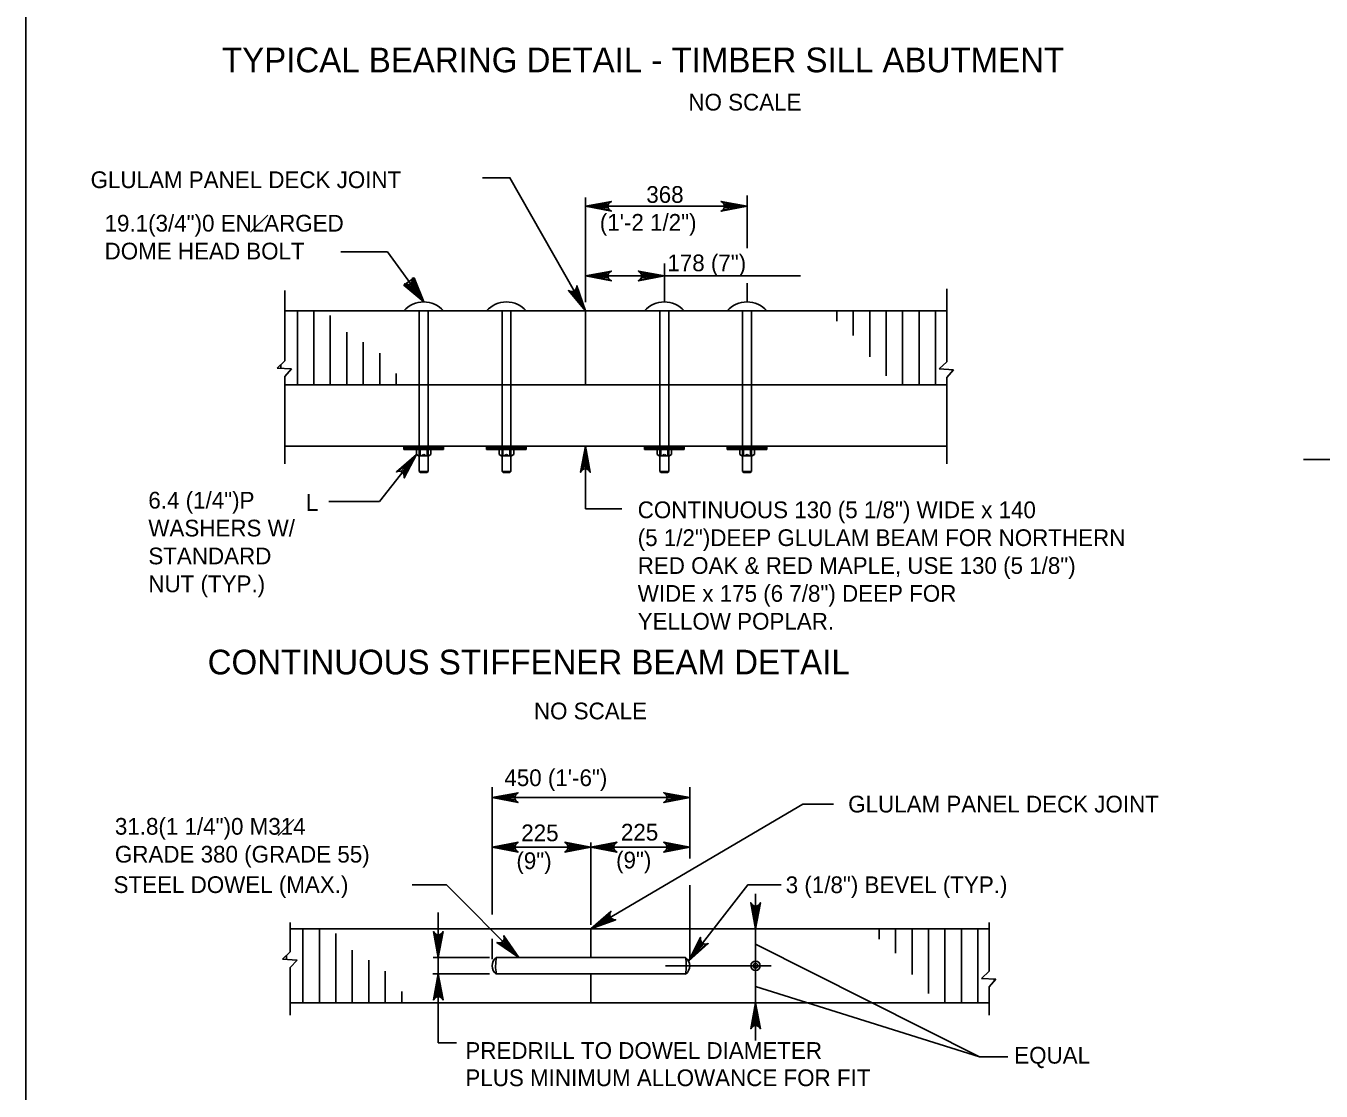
# Model space of a CAD drawing. Extents: x 638268 to 640277, y 295465 to 298435.
# Drawn here: x 639316.5 to 639548.8, y 296279.1 to 296470.2 of the extents above; entities that cross this region are included whole.
import ezdxf

# ---------------------------------------------------------------- set-up
doc = ezdxf.new("R2010")
doc.units = 0
for name, color, linetype in [('2', 7, 'Continuous'), ('3', 7, 'Continuous'), ('5', 7, 'Continuous')]:
    doc.layers.add(name, color=color, linetype=linetype)

msp = doc.modelspace()

# ---------------------------------------------------------------- linework, layer by layer
at = {"layer": '2'}
for p, q in [((639316.46, 296074.46), (639316.46, 296638.46)), ((639381.31, 296429.69), (639372.97, 296429.69)), ((639387.81, 296420.68), (639381.31, 296429.69)), ((639481.65, 296423.01), (639481.65, 296409.95)), ((639362.88, 296422.75), (639362.88, 296410.1)), ((639362.88, 296419.08), (639481.65, 296419.08)), ((639387.81, 296419.08), (639384.24, 296419.08)), ((639387.02, 296390.27), (639387.02, 296419.08)), ((639387.81, 296419.08), (639391.38, 296419.08)), ((639388.6, 296419.08), (639388.6, 296390.27)), ((639401.86, 296390.27), (639401.86, 296419.08)), ((639403.43, 296419.08), (639403.43, 296390.27)), ((639416.81, 296405.8), (639416.81, 296419.08)), ((639430.19, 296390.27), (639430.19, 296419.08)), ((639431.76, 296419.08), (639431.76, 296390.27)), ((639445.02, 296390.27), (639445.02, 296419.08)), ((639446.6, 296419.08), (639446.6, 296390.27)), ((639362.88, 296410.1), (639361.5, 296408.8)), ((639481.65, 296409.95), (639480.27, 296408.65)), ((639361.5, 296408.8), (639364.1, 296408.66)), ((639364.1, 296408.66), (639362.88, 296407.29)), ((639362.88, 296407.29), (639362.88, 296391.6)), ((639480.27, 296408.65), (639482.87, 296408.51)), ((639482.87, 296408.51), (639481.65, 296407.14)), ((639481.65, 296407.14), (639481.65, 296391.6)), ((639362.88, 296405.8), (639481.65, 296405.8)), ((639362.88, 296394.77), (639481.65, 296394.77)), ((639386.51, 296394.18), (639386.51, 296393.29)), ((639389.12, 296394.18), (639386.51, 296394.18)), ((639386.51, 296393.29), (639386.88, 296393.07)), ((639386.88, 296393.07), (639388.74, 296393.07)), ((639387.2, 296393.07), (639387.2, 296394.18)), ((639388.43, 296393.07), (639388.43, 296394.18)), ((639388.74, 296393.07), (639389.12, 296393.29)), ((639389.12, 296394.18), (639389.12, 296393.29)), ((639403.95, 296394.18), (639401.34, 296394.18)), ((639401.34, 296394.18), (639401.34, 296393.29)), ((639401.34, 296393.29), (639401.72, 296393.07)), ((639401.72, 296393.07), (639403.57, 296393.07)), ((639402.03, 296393.07), (639402.03, 296394.18)), ((639403.26, 296393.07), (639403.26, 296394.18)), ((639403.57, 296393.07), (639403.95, 296393.29)), ((639403.95, 296394.18), (639403.95, 296393.29)), ((639432.28, 296394.18), (639429.67, 296394.18)), ((639429.67, 296394.18), (639429.67, 296393.29)), ((639429.67, 296393.29), (639430.05, 296393.07)), ((639430.05, 296393.07), (639431.9, 296393.07)), ((639430.36, 296393.07), (639430.36, 296394.18)), ((639431.59, 296393.07), (639431.59, 296394.18)), ((639431.9, 296393.07), (639432.28, 296393.29)), ((639432.28, 296394.18), (639432.28, 296393.29)), ((639447.12, 296394.18), (639444.51, 296394.18)), ((639444.51, 296394.18), (639444.51, 296393.29)), ((639444.51, 296393.29), (639444.88, 296393.07)), ((639444.88, 296393.07), (639446.74, 296393.07)), ((639445.2, 296393.07), (639445.2, 296394.18)), ((639446.43, 296393.07), (639446.43, 296394.18)), ((639446.74, 296393.07), (639447.12, 296393.29)), ((639447.12, 296394.18), (639447.12, 296393.29)), ((639387.22, 296390.07), (639387.02, 296390.27)), ((639388.6, 296390.27), (639387.02, 296390.27)), ((639388.4, 296390.07), (639387.22, 296390.07)), ((639388.6, 296390.27), (639388.4, 296390.07)), ((639403.43, 296390.27), (639401.86, 296390.27)), ((639402.05, 296390.07), (639401.86, 296390.27)), ((639403.24, 296390.07), (639402.05, 296390.07)), ((639403.43, 296390.27), (639403.24, 296390.07)), ((639431.76, 296390.27), (639430.19, 296390.27)), ((639430.38, 296390.07), (639430.19, 296390.27)), ((639431.57, 296390.07), (639430.38, 296390.07)), ((639431.76, 296390.27), (639431.57, 296390.07)), ((639446.6, 296390.27), (639445.02, 296390.27)), ((639445.22, 296390.07), (639445.02, 296390.27)), ((639446.4, 296390.07), (639445.22, 296390.07)), ((639446.6, 296390.27), (639446.4, 296390.07)), ((639363.88, 296309.32), (639363.88, 296304.05)), ((639489.23, 296309.32), (639489.23, 296300.61)), ((639363.88, 296308.22), (639489.23, 296308.22)), ((639417.81, 296303.05), (639417.81, 296308.22)), ((639363.88, 296304.05), (639362.5, 296302.75)), ((639362.5, 296302.75), (639365.1, 296302.6)), ((639365.1, 296302.6), (639363.88, 296301.24)), ((639363.88, 296301.24), (639363.88, 296292.73)), ((639417.81, 296294.93), (639417.81, 296300.1)), ((639489.23, 296300.61), (639487.86, 296299.3)), ((639487.86, 296299.3), (639490.46, 296299.16)), ((639490.46, 296299.16), (639489.23, 296297.79)), ((639489.23, 296297.79), (639489.23, 296292.73)), ((639363.88, 296294.93), (639489.23, 296294.93))]:
    msp.add_line(p, q, dxfattribs=at)
for points in [[(639387.81, 296420.68), (639386.09, 296424.99), (639384.27, 296423.67)], [(639435.31, 296302.43), (639435.4, 296302.51), (639435.36, 296302.54)]]:
    msp.add_lwpolyline(points, close=True, dxfattribs=at)
msp.add_lwpolyline([(639435.31, 296302.43), (639445.93, 296316.07), (639451.95, 296316.07)], dxfattribs=at)
for centre, radius, start, end in [((639387.81, 296415.89), 4.79, 41.8701, 138.1299), ((639387.16, 296394.16), 1.08, 233, 307), ((639388.46, 296394.16), 1.08, 233, 307), ((639401.99, 296394.16), 1.08, 233, 307), ((639403.3, 296394.16), 1.08, 233, 307), ((639430.32, 296394.16), 1.08, 233, 307), ((639431.63, 296394.16), 1.08, 233, 307), ((639445.16, 296394.16), 1.08, 233, 307), ((639446.46, 296394.16), 1.08, 233, 307)]:
    msp.add_arc(centre, radius, start, end, dxfattribs=at)
at = {"layer": '3'}
for p, q in [((639356.76, 296433.17), (639359.83, 296436.24)), ((639379.86, 296384.86), (639370.8, 296384.86)), ((639416.81, 296383.57), (639423.36, 296383.57)), ((639400.09, 296310.78), (639400.09, 296333.61)), ((639435.53, 296320.85), (639435.53, 296333.61)), ((639400.09, 296331.74), (639435.53, 296331.74)), ((639361.71, 296324.97), (639364.53, 296327.79)), ((639417.81, 296308.94), (639417.81, 296323.67)), ((639400.09, 296322.86), (639435.53, 296322.86)), ((639385.76, 296316.09), (639391.89, 296316.09)), ((639404.87, 296303.05), (639391.89, 296316.09)), ((639435.53, 296302.73), (639435.53, 296316.06)), ((639447.34, 296314.49), (639447.34, 296288.17)), ((639390.41, 296311.14), (639390.41, 296287.74)), ((639400.09, 296302.73), (639400.09, 296306.42)), ((639447.34, 296305.48), (639487.49, 296285.22)), ((639399.6, 296303.05), (639389.49, 296303.05)), ((639399.6, 296300.1), (639389.44, 296300.1)), ((639450.14, 296301.58), (639431.2, 296301.58)), ((639447.34, 296297.84), (639487.49, 296285.22)), ((639390.41, 296287.74), (639393.7, 296287.74)), ((639487.49, 296285.22), (639492.62, 296285.22))]:
    msp.add_line(p, q, dxfattribs=at)
for points in [[(639416.81, 296419.08), (639403.28, 296442.95), (639398.36, 296442.95)], [(639387.81, 296420.68), (639384.38, 296423.95), (639384.79, 296423.8), (639385.15, 296423.83), (639385.43, 296423.97), (639385.66, 296424.2), (639385.8, 296424.53), (639385.79, 296424.97), (639387.81, 296420.68), (639385.8, 296424.53), (639385.66, 296424.2), (639387.81, 296420.68), (639385.43, 296423.97), (639385.15, 296423.83), (639387.81, 296420.68), (639384.79, 296423.8)], [(639416.81, 296419.08), (639413.76, 296422.72), (639414.16, 296422.53), (639414.52, 296422.52), (639414.82, 296422.63), (639415.06, 296422.82), (639415.25, 296423.14), (639415.29, 296423.57), (639416.81, 296419.08), (639415.25, 296423.14), (639415.06, 296422.82), (639416.81, 296419.08), (639414.82, 296422.63), (639414.52, 296422.52), (639416.81, 296419.08), (639414.16, 296422.53)], [(639386.51, 296393.29), (639379.86, 296384.86)], [(639386.51, 296393.29), (639384.31, 296389.09), (639384.33, 296389.53), (639384.2, 296389.87), (639383.99, 296390.1), (639383.71, 296390.25), (639383.35, 296390.3), (639382.93, 296390.17), (639386.51, 296393.29), (639383.35, 296390.3), (639383.71, 296390.25), (639386.51, 296393.29), (639383.99, 296390.1), (639384.2, 296389.87), (639386.51, 296393.29), (639384.33, 296389.53)], [(639416.81, 296394.77), (639417.68, 296390.11), (639417.43, 296390.47), (639417.12, 296390.66), (639416.81, 296390.71), (639416.5, 296390.66), (639416.18, 296390.47), (639415.94, 296390.11), (639416.81, 296394.77), (639416.18, 296390.47), (639416.5, 296390.66), (639416.81, 296394.77), (639416.81, 296390.71), (639417.12, 296390.66), (639416.81, 296394.77), (639417.43, 296390.47)], [(639416.81, 296394.77), (639416.81, 296383.57)], [(639400.09, 296331.74), (639404.75, 296332.62), (639404.4, 296332.37), (639404.21, 296332.06), (639404.16, 296331.74), (639404.21, 296331.43), (639404.4, 296331.12), (639404.75, 296330.87), (639400.09, 296331.74), (639404.4, 296331.12), (639404.21, 296331.43), (639400.09, 296331.74), (639404.16, 296331.74), (639404.21, 296332.06), (639400.09, 296331.74), (639404.4, 296332.37)], [(639435.53, 296331.74), (639430.87, 296330.87), (639431.22, 296331.12), (639431.41, 296331.43), (639431.46, 296331.74), (639431.41, 296332.06), (639431.22, 296332.37), (639430.87, 296332.62), (639435.53, 296331.74), (639431.22, 296332.37), (639431.41, 296332.06), (639435.53, 296331.74), (639431.46, 296331.74), (639431.41, 296331.43), (639435.53, 296331.74), (639431.22, 296331.12)], [(639417.81, 296308.22), (639455.79, 296330.58), (639461.32, 296330.58)], [(639400.09, 296322.86), (639404.75, 296323.73), (639404.4, 296323.48), (639404.21, 296323.17), (639404.16, 296322.86), (639404.21, 296322.54), (639404.4, 296322.23), (639404.75, 296321.98), (639400.09, 296322.86), (639404.4, 296322.23), (639404.21, 296322.54), (639400.09, 296322.86), (639404.16, 296322.86), (639404.21, 296323.17), (639400.09, 296322.86), (639404.4, 296323.48)], [(639417.81, 296322.86), (639413.15, 296321.98), (639413.51, 296322.23), (639413.69, 296322.54), (639413.75, 296322.86), (639413.69, 296323.17), (639413.51, 296323.48), (639413.15, 296323.73), (639417.81, 296322.86), (639413.51, 296323.48), (639413.69, 296323.17), (639417.81, 296322.86), (639413.75, 296322.86), (639413.69, 296322.54), (639417.81, 296322.86), (639413.51, 296322.23)], [(639417.81, 296322.86), (639422.47, 296321.98), (639422.11, 296322.23), (639421.93, 296322.54), (639421.87, 296322.86), (639421.93, 296323.17), (639422.11, 296323.48), (639422.47, 296323.73), (639417.81, 296322.86), (639422.11, 296323.48), (639421.93, 296323.17), (639417.81, 296322.86), (639421.87, 296322.86), (639421.93, 296322.54), (639417.81, 296322.86), (639422.11, 296322.23)], [(639435.53, 296322.86), (639430.87, 296321.98), (639431.22, 296322.23), (639431.41, 296322.54), (639431.46, 296322.86), (639431.41, 296323.17), (639431.22, 296323.48), (639430.87, 296323.73), (639435.53, 296322.86), (639431.22, 296323.48), (639431.41, 296323.17), (639435.53, 296322.86), (639431.46, 296322.86), (639431.41, 296322.54), (639435.53, 296322.86), (639431.22, 296322.23)], [(639447.34, 296308.21), (639446.47, 296312.87), (639446.71, 296312.51), (639447.03, 296312.32), (639447.34, 296312.27), (639447.65, 296312.32), (639447.96, 296312.51), (639448.21, 296312.87), (639447.34, 296308.21), (639447.96, 296312.51), (639447.65, 296312.32), (639447.34, 296308.21), (639447.34, 296312.27), (639447.03, 296312.32), (639447.34, 296308.21), (639446.71, 296312.51)], [(639417.81, 296308.22), (639421.38, 296311.33), (639421.2, 296310.94), (639421.2, 296310.58), (639421.31, 296310.28), (639421.52, 296310.04), (639421.83, 296309.86), (639422.27, 296309.83), (639417.81, 296308.22), (639421.83, 296309.86), (639421.52, 296310.04), (639417.81, 296308.22), (639421.31, 296310.28), (639421.2, 296310.58), (639417.81, 296308.22), (639421.2, 296310.94)], [(639390.41, 296303.05), (639389.54, 296307.71), (639389.79, 296307.35), (639390.1, 296307.17), (639390.41, 296307.11), (639390.73, 296307.17), (639391.04, 296307.35), (639391.29, 296307.71), (639390.41, 296303.05), (639391.04, 296307.35), (639390.73, 296307.17), (639390.41, 296303.05), (639390.41, 296307.11), (639390.1, 296307.17), (639390.41, 296303.05), (639389.79, 296307.35)], [(639404.87, 296303.05), (639400.96, 296305.74), (639401.39, 296305.66), (639401.74, 296305.75), (639402, 296305.93), (639402.18, 296306.19), (639402.27, 296306.54), (639402.2, 296306.97), (639404.87, 296303.05), (639402.27, 296306.54), (639402.18, 296306.19), (639404.87, 296303.05), (639402, 296305.93), (639401.74, 296305.75), (639404.87, 296303.05), (639401.39, 296305.66)], [(639435.31, 296302.43), (639437.48, 296306.65), (639437.46, 296306.21), (639437.59, 296305.87), (639437.8, 296305.64), (639438.08, 296305.49), (639438.44, 296305.44), (639438.86, 296305.57), (639435.31, 296302.43), (639438.44, 296305.44), (639438.08, 296305.49), (639435.31, 296302.43), (639437.8, 296305.64), (639437.59, 296305.87), (639435.31, 296302.43), (639437.46, 296306.21)], [(639390.41, 296300.1), (639391.29, 296295.44), (639391.04, 296295.79), (639390.73, 296295.98), (639390.41, 296296.03), (639390.1, 296295.98), (639389.79, 296295.79), (639389.54, 296295.44), (639390.41, 296300.1), (639389.79, 296295.79), (639390.1, 296295.98), (639390.41, 296300.1), (639390.41, 296296.03), (639390.73, 296295.98), (639390.41, 296300.1), (639391.04, 296295.79)], [(639447.34, 296294.93), (639448.21, 296290.27), (639447.96, 296290.63), (639447.65, 296290.81), (639447.34, 296290.87), (639447.03, 296290.81), (639446.71, 296290.63), (639446.47, 296290.27), (639447.34, 296294.93), (639446.71, 296290.63), (639447.03, 296290.81), (639447.34, 296294.93), (639447.34, 296290.87), (639447.65, 296290.81), (639447.34, 296294.93), (639447.96, 296290.63)]]:
    msp.add_lwpolyline(points, dxfattribs=at)
for points in [[(639416.81, 296419.08), (639416.75, 296419.19), (639416.71, 296419.15)], [(639386.51, 296393.29), (639386.41, 296393.22), (639386.46, 296393.18)], [(639416.81, 296394.77), (639416.78, 296394.66), (639416.84, 296394.66)], [(639417.81, 296308.22), (639417.93, 296308.25), (639417.9, 296308.3)], [(639403.2, 296305.39), (639402.53, 296304.73), (639404.87, 296303.05)]]:
    msp.add_lwpolyline(points, close=True, dxfattribs=at)
for radius in [0.833, 0.417]:
    msp.add_circle((639447.34, 296301.58), radius, dxfattribs=at)
at = {"layer": '5'}
for p, q in [((639416.81, 296420.62), (639416.81, 296439.43)), ((639445.81, 296430.35), (639445.81, 296439.79)), ((639416.81, 296420.62), (639416.81, 296439.07)), ((639416.81, 296437.85), (639445.81, 296437.85)), ((639445.81, 296437.85), (639445.81, 296437.85)), ((639416.81, 296420.62), (639416.81, 296429.77)), ((639416.81, 296425.34), (639455.41, 296425.34)), ((639430.98, 296420.62), (639430.98, 296427.56)), ((639430.98, 296425.34), (639430.98, 296425.34)), ((639445.81, 296420.62), (639445.81, 296424.05)), ((639365.16, 296405.8), (639365.16, 296419.08)), ((639368.11, 296405.8), (639368.11, 296419.08)), ((639402.65, 296419.08), (639399.08, 296419.08)), ((639402.65, 296419.08), (639406.21, 296419.08)), ((639416.81, 296419.08), (639416.81, 296419.08)), ((639430.98, 296419.08), (639427.41, 296419.08)), ((639430.98, 296419.08), (639430.98, 296419.08)), ((639430.98, 296419.08), (639434.54, 296419.08)), ((639445.81, 296419.08), (639442.24, 296419.08)), ((639445.81, 296419.08), (639445.81, 296419.08)), ((639445.81, 296419.08), (639449.38, 296419.08)), ((639461.91, 296417.21), (639461.91, 296419.08)), ((639464.87, 296414.68), (639464.87, 296419.08)), ((639467.82, 296410.85), (639467.82, 296419.08)), ((639470.77, 296407.44), (639470.77, 296419.08)), ((639473.72, 296405.86), (639473.72, 296419.08)), ((639476.68, 296405.8), (639476.68, 296419.08)), ((639479.63, 296405.8), (639479.63, 296419.08)), ((639371.06, 296405.8), (639371.06, 296418.23)), ((639374.01, 296405.8), (639374.01, 296415.23)), ((639376.97, 296405.81), (639376.97, 296413.44)), ((639379.92, 296405.81), (639379.92, 296411.5)), ((639362.2, 296408.76), (639362.2, 296409.47)), ((639382.87, 296405.81), (639382.87, 296407.85)), ((639482.58, 296408.19), (639482.58, 296408.52)), ((639385.82, 296405.81), (639385.82, 296405.93)), ((639451.95, 296405.8), (639451.95, 296405.8)), ((639384.24, 296394.77), (639384.24, 296394.18)), ((639384.24, 296394.48), (639391.38, 296394.48)), ((639384.24, 296394.18), (639391.38, 296394.18)), ((639391.38, 296394.77), (639391.38, 296394.18)), ((639399.08, 296394.77), (639399.08, 296394.18)), ((639399.08, 296394.48), (639406.21, 296394.48)), ((639399.08, 296394.18), (639406.21, 296394.18)), ((639406.21, 296394.77), (639406.21, 296394.18)), ((639427.41, 296394.77), (639427.41, 296394.18)), ((639427.41, 296394.48), (639434.54, 296394.48)), ((639427.41, 296394.18), (639434.54, 296394.18)), ((639434.54, 296394.77), (639434.54, 296394.18)), ((639442.24, 296394.77), (639442.24, 296394.18)), ((639442.24, 296394.48), (639449.38, 296394.48)), ((639442.24, 296394.18), (639449.38, 296394.18)), ((639449.38, 296394.77), (639449.38, 296394.18)), ((639588.32, 296392.38), (639545.62, 296392.38)), ((639366.16, 296294.93), (639366.16, 296308.22)), ((639369.11, 296294.93), (639369.11, 296308.22)), ((639372.06, 296294.93), (639372.06, 296307.36)), ((639469.5, 296306.34), (639469.5, 296308.22)), ((639472.45, 296303.81), (639472.45, 296308.22)), ((639475.41, 296299.98), (639475.41, 296308.22)), ((639478.36, 296296.57), (639478.36, 296308.22)), ((639481.31, 296294.99), (639481.31, 296308.22)), ((639484.27, 296294.93), (639484.27, 296308.22)), ((639487.22, 296294.93), (639487.22, 296308.22)), ((639363.2, 296302.71), (639363.2, 296303.41)), ((639375.01, 296294.94), (639375.01, 296304.37)), ((639377.97, 296294.94), (639377.97, 296302.57)), ((639400.86, 296303.05), (639434.76, 296303.05)), ((639380.92, 296294.94), (639380.92, 296300.63)), ((639400.84, 296300.1), (639434.78, 296300.1)), ((639490.17, 296298.84), (639490.17, 296299.17)), ((639383.87, 296294.94), (639383.87, 296296.98)), ((639386.82, 296294.94), (639386.82, 296295.06))]:
    msp.add_line(p, q, dxfattribs=at)
for points in [[(639416.81, 296437.85), (639421.47, 296438.72), (639421.11, 296438.47), (639420.93, 296438.16), (639420.87, 296437.85), (639420.93, 296437.53), (639421.11, 296437.22), (639421.47, 296436.97), (639416.81, 296437.85), (639421.11, 296437.22), (639420.93, 296437.53), (639416.81, 296437.85), (639420.87, 296437.85), (639420.93, 296438.16), (639416.81, 296437.85), (639421.11, 296438.47)], [(639445.81, 296437.85), (639441.15, 296436.97), (639441.51, 296437.22), (639441.69, 296437.53), (639441.75, 296437.85), (639441.69, 296438.16), (639441.51, 296438.47), (639441.15, 296438.72), (639445.81, 296437.85), (639441.51, 296438.47), (639441.69, 296438.16), (639445.81, 296437.85), (639441.75, 296437.85), (639441.69, 296437.53), (639445.81, 296437.85), (639441.51, 296437.22)], [(639416.81, 296425.34), (639421.47, 296426.22), (639421.11, 296425.97), (639420.93, 296425.66), (639420.87, 296425.34), (639420.93, 296425.03), (639421.11, 296424.72), (639421.47, 296424.47), (639416.81, 296425.34), (639421.11, 296424.72), (639420.93, 296425.03), (639416.81, 296425.34), (639420.87, 296425.34), (639420.93, 296425.66), (639416.81, 296425.34), (639421.11, 296425.97)], [(639430.98, 296425.34), (639426.32, 296424.47), (639426.67, 296424.72), (639426.86, 296425.03), (639426.91, 296425.34), (639426.86, 296425.66), (639426.67, 296425.97), (639426.32, 296426.22), (639430.98, 296425.34), (639426.67, 296425.97), (639426.86, 296425.66), (639430.98, 296425.34), (639426.91, 296425.34), (639426.86, 296425.03), (639430.98, 296425.34), (639426.67, 296424.72)]]:
    msp.add_lwpolyline(points, dxfattribs=at)
for points in [[(639419.76, 296438.34), (639419.76, 296437.35), (639416.81, 296437.85)], [(639442.86, 296438.34), (639442.86, 296437.35), (639445.81, 296437.85)], [(639419.76, 296425.83), (639419.76, 296424.85), (639416.81, 296425.34)], [(639428.02, 296425.83), (639428.02, 296424.85), (639430.98, 296425.34)]]:
    msp.add_lwpolyline(points, close=True, dxfattribs=at)
for centre, radius, start, end in [((639402.65, 296415.89), 4.79, 41.8701, 138.1299), ((639430.98, 296415.89), 4.79, 41.8701, 138.1299), ((639445.81, 296415.89), 4.79, 41.8701, 138.1299), ((639401.91, 296301.56), 1.82, 125.2575, 233.7233), ((639408.34, 296301.51), 7.63, 168.3368, 190.6439), ((639433.71, 296301.56), 1.82, 306.2767, 54.7425), ((639427.28, 296301.51), 7.63, 349.3561, 11.6632)]:
    msp.add_arc(centre, radius, start, end, dxfattribs=at)

# ---------------------------------------------------------------- texts
at = {"layer": '2'}
msp.add_text('TYPICAL BEARING DETAIL - TIMBER SILL ABUTMENT', height=4.4292, dxfattribs=at).set_placement((639351.63, 296461.88))
at = {"layer": '3'}
for s, height, p in [('NO SCALE', 3, (639435.29, 296455.02)), ('GLULAM PANEL DECK JOINT', 3, (639328.06, 296441.1)), ('19.1(3/4")0 ENLARGED', 3, (639330.57, 296433.3)), ('DOME HEAD BOLT', 3, (639330.57, 296428.3)), ('6.4 (1/4")P', 3, (639338.42, 296383.6)), ('L', 3, (639366.67, 296383.19)), ('CONTINUOUS 130 (5 1/8") WIDE x 140', 3, (639426.2, 296381.88)), ('WASHERS W/ ', 3, (639338.42, 296378.6)), ('(5 1/2")DEEP GLULAM BEAM FOR NORTHERN', 3, (639426.2, 296376.88)), ('STANDARD', 3, (639338.42, 296373.6)), ('RED OAK & RED MAPLE, USE 130 (5 1/8")', 3, (639426.2, 296371.88)), ('NUT (TYP.)', 3, (639338.42, 296368.6)), ('WIDE x 175 (6 7/8") DEEP FOR', 3, (639426.2, 296366.88)), ('YELLOW POPLAR.', 3, (639426.2, 296361.88)), ('CONTINUOUS STIFFENER BEAM DETAIL', 4.4292, (639349.06, 296353.85)), ('NO SCALE', 3, (639407.58, 296345.79)), ('450 (1\'-6")', 3, (639402.28, 296333.81)), ('GLULAM PANEL DECK JOINT', 3, (639463.96, 296329.08)), ('31.8(1 1/4")0 M314', 3, (639332.42, 296325.09)), ('225', 3, (639405.31, 296323.92)), ('225', 3, (639423.19, 296324.04)), ('GRADE 380 (GRADE 55)', 3, (639332.42, 296320.09)), ('(9")', 3, (639404.44, 296318.92)), ('(9")', 3, (639422.32, 296319.04)), ('STEEL DOWEL (MAX.)', 3, (639332.18, 296314.63)), ('3 (1/8") BEVEL (TYP.)', 3, (639452.75, 296314.61)), ('PREDRILL TO DOWEL DIAMETER', 3, (639395.29, 296284.87)), ('EQUAL', 3, (639493.74, 296284.02)), ('PLUS MINIMUM ALLOWANCE FOR FIT', 3, (639395.29, 296279.98))]:
    msp.add_text(s, height=height, dxfattribs=at).set_placement(p)
at = {"layer": '5'}
for s, p in [('368', (639427.74, 296438.45)), ('(1\'-2 1/2")', (639419.4, 296433.45)), ('178 (7")', (639431.52, 296426.18))]:
    msp.add_text(s, height=3, dxfattribs=at).set_placement(p)

doc.saveas('drawing.dxf')
